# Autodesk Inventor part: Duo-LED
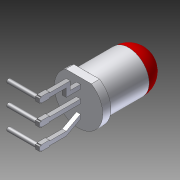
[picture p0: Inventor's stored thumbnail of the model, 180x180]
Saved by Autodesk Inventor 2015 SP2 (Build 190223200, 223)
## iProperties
Created: 2016-03
Part Number: Duo-LED
Material: Allgemein
Document SubType Name: Modeling
Designer: ryll
Density: 1 g/cm^3
Appearance: Vorgabe
Title: 59.STEP
Description: STEP AP214
Creation Date: 2008-08-27
Sending System: SolidWorks 2008
Preprocessor: SwSTEP 2.0
Author: ryll
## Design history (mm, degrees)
node "591"
workplane "Arbeitsebene1"
sketch "Skizze1"
  geometry: L1 (2.411, 3.03)-(-2.998, 3.03); L2 (-2.998, 3.03)-(-2.998, -3.074); L3 (-2.998, -3.074)-(2.411, -3.074); L4 (2.411, -3.074)-(2.411, 3.03); 1 further point
  constraints: 8 end point, 2 parallel, 1 horizontal, 1 perpendicular
extrude "Extrusion1" cut sketch "Skizze1" distance "d1" = 20; taper "d2" = 0 deg
sketch "Skizze2"
  geometry: L1 (-3.04, -1.2)-(-2.54, -1.2) reference; L2 (-2.54, -1)-(-2.54, -1.2) reference; L3 (-2.44, -1)-(-2.54, -1) reference; L4 (-2.44, -1)-(-2.44, 0) reference; L5 (-2.44, 0)-(-2.54, 0) reference; L6 (-2.54, 2.05)-(-2.54, 0) reference; L7 (-1.61, 3.8)-(-2.54, 2.05) reference; L8 (-2.11, 3.8)-(-1.61, 3.8) reference; L9 (-3.04, 2.05)-(-2.11, 3.8) reference; L10 (-3.04, 0)-(-3.04, 2.05) reference; L11 (-3.04, 0)-(-3.14, 0) reference; L12 (-3.14, -1)-(-3.14, 0) reference; L13 (-3.04, -1)-(-3.14, -1) reference; L14 (-3.04, -1.2)-(-3.04, -1) reference; L15 (-0.5, -1.2)-(0, -1.2) reference; L16 (0, -1.2)-(0, -1) reference; L17 (0, -1)-(0.1, -1) reference; L18 (0.1, 0)-(0.1, -1) reference; L19 (0, 0)-(0.1, 0) reference; L20 (0, 0)-(0, 3.8) reference; L21 (0, 3.8)-(-0.5, 3.8) reference; L22 (-0.5, 3.8)-(-0.5, 0) reference; L23 (-0.6, 0)-(-0.5, 0) reference; L24 (-0.6, 0)-(-0.6, -1) reference; L25 (-0.6, -1)-(-0.5, -1) reference; L26 (-0.5, -1)-(-0.5, -1.2) reference; L27 (2.04, -1.2)-(2.54, -1.2) reference; L28 (2.54, -1)-(2.54, -1.2) reference; L29 (2.54, -1)-(2.64, -1) reference; L30 (2.64, 0)-(2.64, -1) reference; L31 (2.54, 0)-(2.64, 0) reference; L32 (2.54, 2.55)-(2.54, 0) reference; L33 (1.54, 2.55)-(2.54, 2.55) reference; L34 (1.54, 3.8)-(1.54, 2.55) reference; L35 (1.04, 3.8)-(1.54, 3.8) reference; L36 (1.04, 2.05)-(1.04, 3.8) reference; L37 (2.04, 2.05)-(1.04, 2.05) reference; L38 (2.04, 0)-(2.04, 2.05) reference; L39 (1.94, 0)-(2.04, 0) reference; L40 (1.94, 0)-(1.94, -1) reference; L41 (1.94, -1)-(2.04, -1) reference; L42 (2.04, -1.2)-(2.04, -1) reference; L43 (-2.54, -1)-(-2.54, -1.2) reference; L44 (2.54, -1)-(2.54, -1.2) reference; L45 (2.04, -1.2)-(2.54, -1.2) reference; L46 (-0.5, -1.2)-(0, -1.2) reference; L47 (-3.04, -1.2)-(-2.54, -1.2) reference; C1 r 0.25 at (2.29, -0.95); C2 r 0.25 at (-0.25, -0.95); C3 r 0.25 at (-2.79, -0.95); 1 further point
  constraints: 6 tangent, 3 centre point
  dimensions: "d6" = 0.5 diameter of C1; "d7" = 0.5 diameter of C2; "d8" = 0.5 diameter of C3
extrude "Extrusion2" join sketch "Skizze2" distance "d4" = 3.5; taper "d5" = 0 deg
node "NONE"
node "Basis1"
node "Projizierte Kontur1"
node "Projizierte Kontur2"
node "Projizierte Kontur3"
other parameters: "d0" = -6
